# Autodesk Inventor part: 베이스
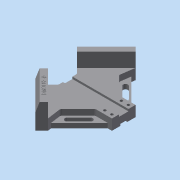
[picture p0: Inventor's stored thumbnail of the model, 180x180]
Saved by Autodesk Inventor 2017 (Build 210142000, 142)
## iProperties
Part Number: 베이스
Material: 일반
Document SubType Name: Modeling
Designer: 222
Density: 1 g/cm^3
Appearance: 기본값
Author: 222
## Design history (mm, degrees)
sketch "스케치1"
  geometry: L1 (-84.853, 0)-(0, 84.853); L2 (0, 84.853)-(84.853, 0); L3 (84.853, 0)-(0, -84.853); L4 (0, -84.853)-(-84.853, 0); L5 (-84.853, 0)-(84.853, 0); L6 (0, 84.853)-(0, -84.853); L7 (-84.853, 0)-(35.147, 0); 1 further point
  constraints: 14 end point, 2 midpoint, 2 parallel, 1 equal length, 1 horizontal, 1 perpendicular
  dimensions: "d0" = 120 distance of L1.start L1.end; "d1" = 45 deg angle of L7 L1; "d2" = 120 distance of L1.end L2.end
extrude "돌출1" new body sketch "스케치1" distance "d3" = 18; taper "d4" = 0 deg
sketch "스케치2"
  geometry: L1 (0, -84.853)-(-84.853, 0) reference; L2 (-84.853, 0)-(0, 84.853) reference; L3 (0, 84.853)-(84.853, 0) reference; L4 (84.853, 0)-(0, -84.853) reference; L5 (64.853, -20)-(64.853, 20); 1 further point
  constraints: 2 end point, 2 point on line, 1 vertical
  dimensions: "d5" = 20 distance from line of L3.end L5
extrude "돌출2" cut sketch "스케치2" stored distance "d6" = 18; taper "d7" = 0 deg
sketch "스케치3"
  geometry: L1 (-49.497, -35.355)-(-30.147, -16.005); L2 (-30.147, -16.005)-(-30.147, 16.005); L3 (-30.147, 16.005)-(-49.497, 35.355); L4 (0, -84.853)-(-84.853, 0) reference; L5 (-84.853, 0)-(0, 84.853) reference; L6 (0, 84.853)-(64.853, 20) reference; L7 (64.853, 20)-(64.853, -20) reference; L8 (64.853, -20)-(0, -84.853) reference; 2 further points
  constraints: 6 end point, 2 parallel, 2 point on line, 1 horizontal alignment, 1 midpoint, 1 perpendicular, 1 vertical
  dimensions: "d9" = 50 distance between parallel lines of L5 L1; "d11" = 95 distance between parallel lines of L7 L2
extrude "돌출3" cut sketch "스케치3" stored distance "d12" = 18; taper "d13" = 0 deg
sketch "스케치4"
  geometry: L1 (64.853, 20)-(64.853, -20) reference; L2 (64.853, -20)-(0, -84.853) reference; L3 (0, -84.853)-(-49.497, -35.355) reference; L4 (-49.497, -35.355)-(-30.147, -16.005) reference; L5 (-30.147, -16.005)-(-30.147, 16.005) reference; L6 (-30.147, 16.005)-(-49.497, 35.355) reference; L7 (-49.497, 35.355)-(0, 84.853) reference; L8 (0, 84.853)-(64.853, 20) reference; L9 (10.607, -74.246)-(-38.891, -24.749); 1 further point
  constraints: 2 end point, 2 point on line, 1 parallel
  dimensions: "d14" = 15 distance between parallel lines of L9 L3
extrude "돌출4" join sketch "스케치4" distance "d15" = 24; taper "d16" = 0 deg
sketch "스케치5"
  geometry: L1 (64.853, 20)-(64.853, -20) reference; L2 (64.853, -20)-(10.607, -74.246) reference; L3 (-38.891, -24.749)-(10.607, -74.246) reference; L4 (-49.497, -35.355)-(-38.891, -24.749) reference; L5 (0, -84.853)-(-49.497, -35.355) reference; L6 (10.607, -74.246)-(0, -84.853) reference; L7 (0, 84.853)-(64.853, 20) reference; L8 (-49.497, 35.355)-(0, 84.853) reference; L9 (-30.147, 16.005)-(-49.497, 35.355) reference; L10 (-30.147, -16.005)-(-30.147, 16.005) reference; L11 (-38.891, -24.749)-(-30.147, -16.005) reference; L12 (10.607, -74.246)-(7.071, -49.497); L13 (7.071, -49.497)-(36.569, -20); L14 (36.569, -20)-(64.853, -20); L15 (9.723, -68.059)-(57.782, -20); L16 (18.385, -49.497)-(38.184, -29.698); L17 (21.213, -52.326)-(41.012, -32.527); L18 (35.355, -26.87)-(15.556, -46.669); A1 r 4 centre (18.385, -49.497) between (15.556, -46.669) and (21.213, -52.326); A2 r 4 centre (38.184, -29.698) between (41.012, -32.527) and (35.355, -26.87); 2 further points
  constraints: 16 end point, 4 parallel, 4 point on circle, 4 tangent, 2 centre point, 2 point on line, 1 horizontal, 1 midpoint
  dimensions: "d17" = 20 distance between parallel lines of L2 L13; "d18" = 30 distance from line of L5 L12.end; "d19" = 5 distance between parallel lines of L2 L15; "d20" = 12 distance between parallel lines of L2 L16; "d21" = 38 distance from line of L16.start L5; "d22" = 28 distance of L16.end L16.start; "d23" = 4 radius of A1
  node "절단 모서리 투영4"
extrude "돌출5" cut sketch "스케치5" stored distance "d24" = 24; taper "d25" = 0 deg
extrude "돌출6" cut sketch "스케치5" distance "d26" = 10; taper "d27" = 0 deg
sketch "스케치7"
  geometry: L1 (3, 6)-(0, 6); L2 (0, 6)-(0, -6); L3 (0, -6)-(3, -6); L4 (3, -6)-(3, 6); L5 (18, 8)-(14.5, 8); L6 (14.5, 8)-(14.5, -8); L7 (14.5, -8)-(18, -8); L8 (18, -8)-(18, 8); L9 (18, -16.005)-(18, 16.005) reference; 3 further points
  constraints: 16 end point, 4 parallel, 3 midpoint, 2 horizontal, 2 perpendicular, 1 coincident, 1 horizontal alignment
  dimensions: "d32" = 12 distance between parallel lines of L3 L1; "d33" = 16 distance of L5.end L6.end; "d34" = 3.5 distance between parallel lines of L8 L6; "d35" = 3 distance between parallel lines of L2 L4
extrude "돌출7" cut sketch "스케치7" stored distance "d36" = 10; taper "d37" = 0 deg
sketch "스케치9"
  geometry: L1 (64.853, 6)-(64.853, 20) reference; 2 further points
  dimensions: "d40" = 14 vertical distance of point (0, 0) point (58.853, 14); "d41" = 6 distance from line of L1 point (58.853, 14)
hole "구멍1" sketch "스케치9" at (58.853, 14) diameter "d42" = 4.5; stored, may be unused: countersink angle "d46" = 90 deg, drill point angle "d48" = 118 deg; dims "d43" = 6, "d44" = 8, "d45" = 8, "d47" = 8
fillet "모깎기1" dims "d55" = 5
sketch "스케치10"
  geometry: L1 (10.607, -74.246)-(-38.891, -24.749) reference; L2 (-38.891, -24.749)-(-49.497, -35.355) reference; 2 further points
  constraints: 1 other
  dimensions: "d56" = 5 distance from line of L1 point (-17.678, -53.033); "d57" = 35 distance from line of point (-17.678, -53.033) L2
feature "엠보싱1" sketch "스케치10" dims "d0" = 120, "d1" = 45 deg, "d2" = 120, "d9" = 50, "d11" = 95, "d58" = 0.5, "d59" = 0
chamfer "모따기1" distance "d60" = 5; stored, may be unused: second distance "d61" = 15, angle "d62" = 45 deg
chamfer "모따기2" distance "d63" = 15; stored, may be unused: second distance "d64" = 5, angle "d65" = 45 deg
fillet "모깎기2" dims "d66" = 5
node "솔리드1"
mirror "미러1"
pattern_linear "직사각형 패턴1" dims "d51" = 12, "d54" = 28
node "절단 모서리 투영1"
node "절단 모서리 투영2"
node "절단 모서리 투영3"
